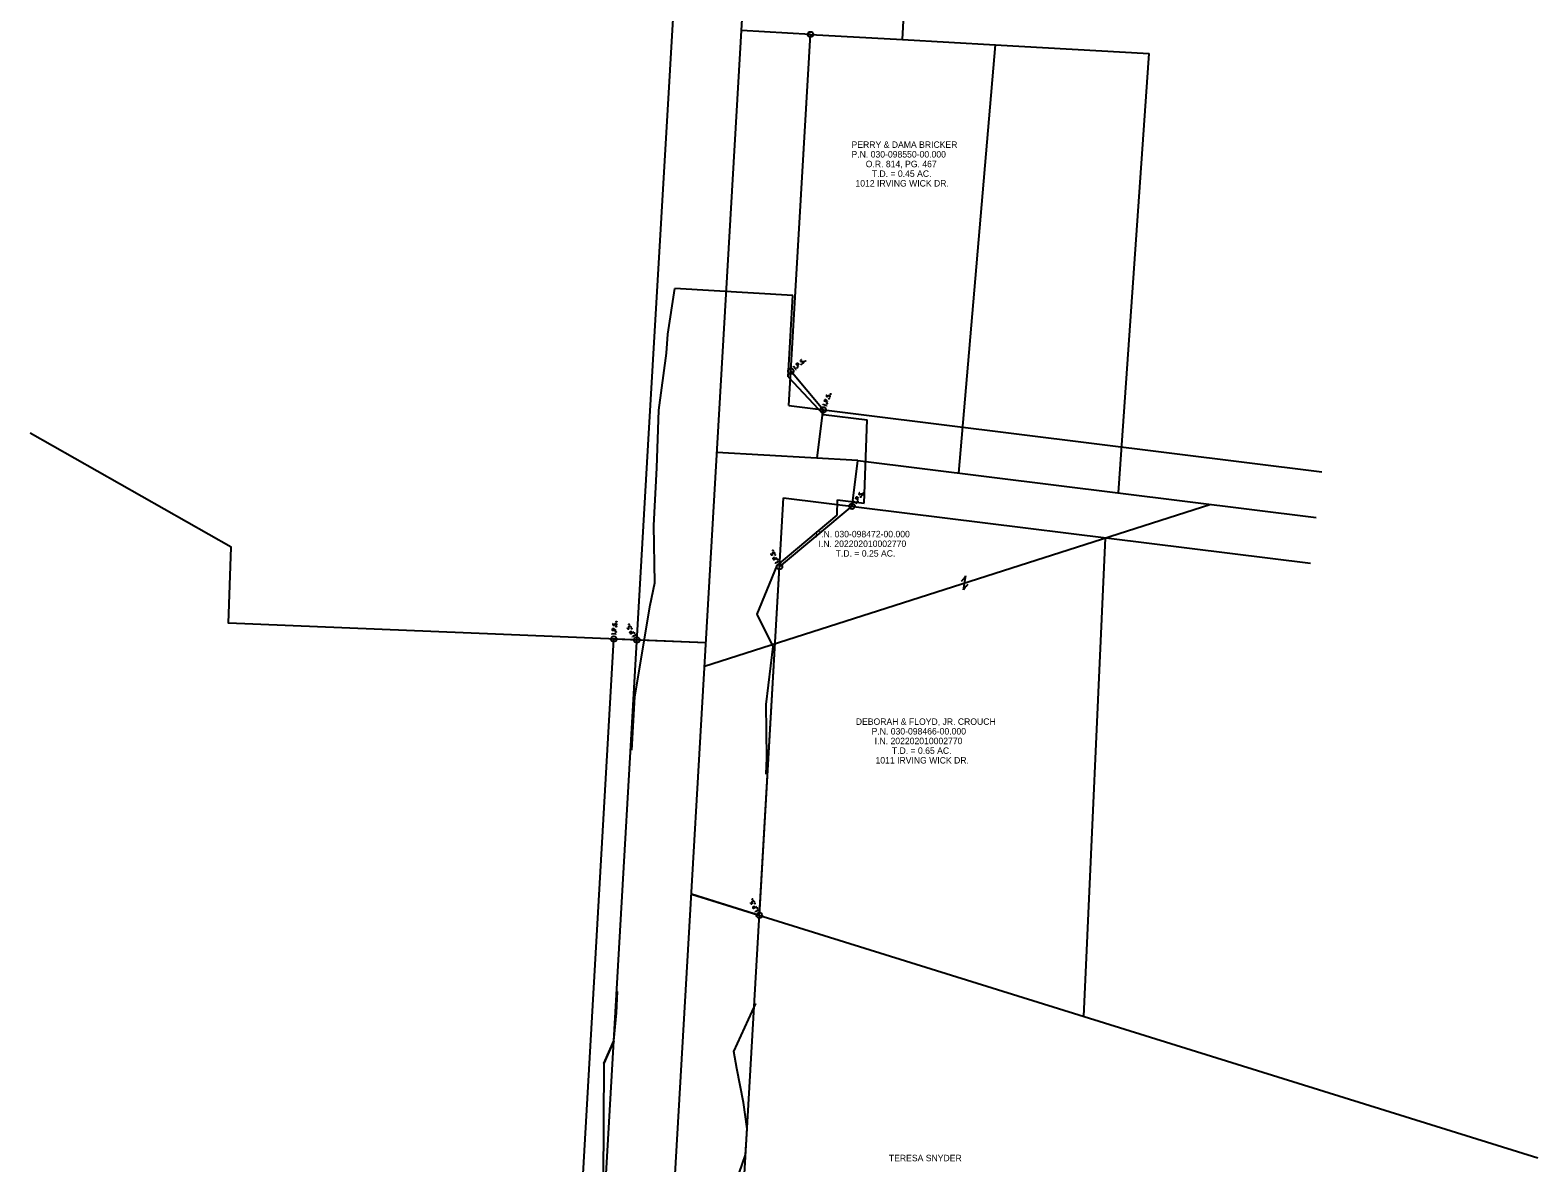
# Model space of a CAD drawing. Extents: x 1972534 to 2012581, y 730948 to 738786.
# Drawn here: x 1973763 to 1974418, y 737810 to 738302 of the extents above; entities that cross this region are included whole.
import ezdxf

# ---------------------------------------------------------------- set-up
doc = ezdxf.new("R2010")
doc.units = 0
for name, color, linetype in [('_CIVIL_CONSTRUCTION', 7, 'Continuous'), ('DR_P_GenericNode', 7, 'Continuous'), ('DR_X_Storm_Sewer', 7, 'Continuous'), ('GE_X_Alignment_1000_Cardinal_Points', 7, 'Continuous'), ('PF_X_Ground_Line', 7, 'Continuous'), ('SC_ProfileRun4', 7, 'Continuous'), ('UT_P_Water', 7, 'Continuous'), ('UT_P_Water_Cells', 7, 'Continuous')]:
    doc.layers.add(name, color=color, linetype=linetype)

msp = doc.modelspace()

# ---------------------------------------------------------------- linework, layer by layer
at = {"layer": 'DR_P_GenericNode'}
for points in [[(1974094.28, 738155.41), (1974094.55, 738155.64)], [(1974095.45, 738154.31), (1974094.42, 738155.53)], [(1974096.65, 738155.32), (1974095.61, 738156.54), (1974096.01, 738156.88), (1974096.06, 738156.91), (1974096.14, 738156.94), (1974096.18, 738156.94), (1974096.22, 738156.94), (1974096.29, 738156.92), (1974096.36, 738156.9), (1974096.44, 738156.84), (1974096.54, 738156.72), (1974096.56, 738156.67), (1974096.6, 738156.6), (1974096.62, 738156.51), (1974096.61, 738156.45), (1974096.6, 738156.41), (1974096.58, 738156.35), (1974096.52, 738156.29), (1974096.12, 738155.94)], [(1974097.97, 738158.4), (1974097.94, 738158.41), (1974097.9, 738158.41), (1974097.8, 738158.37), (1974097.69, 738158.31), (1974097.62, 738158.25), (1974097.6, 738158.23), (1974097.51, 738158.11), (1974097.47, 738157.97), (1974097.48, 738157.85), (1974097.53, 738157.76), (1974097.57, 738157.7), (1974097.66, 738157.64), (1974097.78, 738157.63), (1974098.49, 738157.73), (1974098.56, 738157.73), (1974098.61, 738157.71), (1974098.68, 738157.66), (1974098.73, 738157.6), (1974098.77, 738157.54), (1974098.79, 738157.49), (1974098.82, 738157.43), (1974098.83, 738157.38), (1974098.84, 738157.34), (1974098.84, 738157.29), (1974098.83, 738157.25), (1974098.81, 738157.2), (1974098.8, 738157.17), (1974098.73, 738157.09), (1974098.61, 738156.99), (1974098.52, 738156.95), (1974098.35, 738156.92), (1974098.24, 738156.92)], [(1974097.76, 738156.55), (1974097.8, 738156.58), (1974097.84, 738156.59), (1974097.9, 738156.57), (1974097.94, 738156.52), (1974097.95, 738156.46), (1974097.94, 738156.42), (1974097.9, 738156.39), (1974097.86, 738156.38), (1974097.8, 738156.4), (1974097.76, 738156.45), (1974097.75, 738156.51), (1974097.76, 738156.55)], [(1974099.42, 738157.96), (1974099.46, 738158), (1974099.5, 738158), (1974099.56, 738157.98), (1974099.6, 738157.94), (1974099.61, 738157.88), (1974099.6, 738157.84), (1974099.56, 738157.8), (1974099.52, 738157.8), (1974099.46, 738157.81), (1974099.42, 738157.86), (1974099.41, 738157.92), (1974099.42, 738157.96)], [(1974095.32, 738154.19), (1974095.59, 738154.42)], [(1974096.05, 738155.09), (1974096.09, 738155.13), (1974096.13, 738155.13), (1974096.19, 738155.11), (1974096.23, 738155.06), (1974096.23, 738155), (1974096.23, 738154.96), (1974096.18, 738154.93), (1974096.14, 738154.93), (1974096.08, 738154.94), (1974096.04, 738154.99), (1974096.04, 738155.05), (1974096.05, 738155.09)], [(1974108.98, 738143.25), (1974108.95, 738143.24), (1974108.92, 738143.22), (1974108.85, 738143.14), (1974108.78, 738143.04), (1974108.75, 738142.95), (1974108.74, 738142.92), (1974108.72, 738142.77), (1974108.75, 738142.63), (1974108.82, 738142.53), (1974108.91, 738142.47), (1974108.98, 738142.45), (1974109.08, 738142.43), (1974109.19, 738142.48), (1974109.76, 738142.92), (1974109.82, 738142.95), (1974109.88, 738142.96), (1974109.96, 738142.95), (1974110.03, 738142.93), (1974110.1, 738142.89), (1974110.14, 738142.86), (1974110.19, 738142.82), (1974110.23, 738142.78), (1974110.26, 738142.75), (1974110.28, 738142.7), (1974110.29, 738142.66), (1974110.3, 738142.61), (1974110.3, 738142.58), (1974110.28, 738142.48), (1974110.23, 738142.34), (1974110.17, 738142.25), (1974110.04, 738142.15), (1974109.93, 738142.09)], [(1974110.46, 738143.58), (1974110.48, 738143.63), (1974110.51, 738143.65), (1974110.57, 738143.66), (1974110.63, 738143.64), (1974110.67, 738143.59), (1974110.68, 738143.55), (1974110.66, 738143.5), (1974110.62, 738143.48), (1974110.57, 738143.47), (1974110.51, 738143.49), (1974110.47, 738143.54), (1974110.46, 738143.58)], [(1974107.22, 738138.84), (1974107.35, 738139.17)], [(1974108.79, 738138.45), (1974107.29, 738139)], [(1974109.33, 738139.92), (1974107.83, 738140.47), (1974108.01, 738140.97), (1974108.04, 738141.02), (1974108.1, 738141.08), (1974108.13, 738141.1), (1974108.17, 738141.12), (1974108.24, 738141.14), (1974108.31, 738141.15), (1974108.41, 738141.14), (1974108.55, 738141.09), (1974108.6, 738141.06), (1974108.66, 738141.01), (1974108.73, 738140.94), (1974108.75, 738140.88), (1974108.76, 738140.84), (1974108.77, 738140.78), (1974108.75, 738140.7), (1974108.56, 738140.2)], [(1974108.73, 738138.28), (1974108.85, 738138.61)], [(1974108.92, 738139.42), (1974108.94, 738139.47), (1974108.97, 738139.5), (1974109.03, 738139.51), (1974109.09, 738139.49), (1974109.13, 738139.44), (1974109.14, 738139.4), (1974109.12, 738139.35), (1974109.08, 738139.33), (1974109.03, 738139.31), (1974108.97, 738139.33), (1974108.93, 738139.38), (1974108.92, 738139.42)], [(1974109.7, 738141.53), (1974109.72, 738141.58), (1974109.75, 738141.6), (1974109.81, 738141.62), (1974109.87, 738141.6), (1974109.91, 738141.55), (1974109.92, 738141.51), (1974109.9, 738141.46), (1974109.87, 738141.43), (1974109.81, 738141.42), (1974109.75, 738141.44), (1974109.71, 738141.49), (1974109.7, 738141.53)], [(1974120.36, 738096.91), (1974120.57, 738097.19)], [(1974121.77, 738096.12), (1974120.47, 738097.05)], [(1974122.68, 738097.39), (1974121.38, 738098.32), (1974121.69, 738098.75), (1974121.73, 738098.79), (1974121.79, 738098.84), (1974121.83, 738098.85), (1974121.87, 738098.86), (1974121.95, 738098.86), (1974122.02, 738098.85), (1974122.12, 738098.81), (1974122.24, 738098.72), (1974122.27, 738098.68), (1974122.32, 738098.62), (1974122.37, 738098.54), (1974122.37, 738098.48), (1974122.37, 738098.44), (1974122.36, 738098.38), (1974122.32, 738098.3), (1974122.01, 738097.87)], [(1974121.67, 738095.97), (1974121.87, 738096.26)], [(1974122.15, 738097.02), (1974122.18, 738097.07), (1974122.22, 738097.08), (1974122.28, 738097.08), (1974122.34, 738097.04), (1974122.36, 738096.98), (1974122.36, 738096.94), (1974122.33, 738096.9), (1974122.29, 738096.89), (1974122.23, 738096.89), (1974122.17, 738096.92), (1974122.15, 738096.98), (1974122.15, 738097.02)], [(1974123.22, 738100.7), (1974123.19, 738100.7), (1974123.15, 738100.69), (1974123.06, 738100.63), (1974122.97, 738100.55), (1974122.92, 738100.47), (1974122.9, 738100.45), (1974122.85, 738100.31), (1974122.84, 738100.17), (1974122.87, 738100.04), (1974122.94, 738099.97), (1974123, 738099.92), (1974123.1, 738099.88), (1974123.22, 738099.9), (1974123.88, 738100.18), (1974123.96, 738100.19), (1974124.01, 738100.18), (1974124.08, 738100.15), (1974124.15, 738100.11), (1974124.2, 738100.06), (1974124.23, 738100.02), (1974124.27, 738099.96), (1974124.3, 738099.92), (1974124.32, 738099.88), (1974124.33, 738099.83), (1974124.33, 738099.79), (1974124.33, 738099.74), (1974124.32, 738099.7), (1974124.27, 738099.61), (1974124.18, 738099.49), (1974124.1, 738099.42), (1974123.95, 738099.36), (1974123.83, 738099.33)], [(1974123.46, 738098.85), (1974123.49, 738098.9), (1974123.53, 738098.91), (1974123.59, 738098.91), (1974123.64, 738098.87), (1974123.67, 738098.81), (1974123.67, 738098.77), (1974123.64, 738098.73), (1974123.6, 738098.71), (1974123.54, 738098.72), (1974123.48, 738098.75), (1974123.46, 738098.81), (1974123.46, 738098.85)], [(1974124.73, 738100.63), (1974124.76, 738100.67), (1974124.8, 738100.68), (1974124.86, 738100.68), (1974124.91, 738100.64), (1974124.94, 738100.59), (1974124.94, 738100.55), (1974124.91, 738100.5), (1974124.87, 738100.49), (1974124.81, 738100.49), (1974124.75, 738100.53), (1974124.73, 738100.58), (1974124.73, 738100.63)], [(1974084.62, 738074.24), (1974084.61, 738074.21), (1974084.6, 738074.17), (1974084.62, 738074.07), (1974084.65, 738073.95), (1974084.69, 738073.87), (1974084.7, 738073.84), (1974084.8, 738073.73), (1974084.93, 738073.66), (1974085.05, 738073.63), (1974085.15, 738073.66), (1974085.22, 738073.7), (1974085.3, 738073.76), (1974085.34, 738073.88), (1974085.39, 738074.59), (1974085.41, 738074.67), (1974085.45, 738074.71), (1974085.5, 738074.76), (1974085.57, 738074.8), (1974085.64, 738074.82), (1974085.69, 738074.84), (1974085.76, 738074.84), (1974085.81, 738074.85), (1974085.86, 738074.85), (1974085.91, 738074.83), (1974085.94, 738074.82), (1974085.99, 738074.79), (1974086.01, 738074.77), (1974086.07, 738074.68), (1974086.14, 738074.55), (1974086.16, 738074.45), (1974086.15, 738074.28), (1974086.12, 738074.17)], [(1974085.38, 738075.55), (1974085.35, 738075.6), (1974085.36, 738075.64), (1974085.39, 738075.7), (1974085.45, 738075.72), (1974085.51, 738075.72), (1974085.54, 738075.7), (1974085.57, 738075.65), (1974085.56, 738075.61), (1974085.53, 738075.56), (1974085.48, 738075.53), (1974085.42, 738075.54), (1974085.38, 738075.55)], [(1974087.33, 738072.25), (1974085.9, 738071.52), (1974085.66, 738071.99), (1974085.65, 738072.04), (1974085.63, 738072.12), (1974085.64, 738072.17), (1974085.65, 738072.21), (1974085.68, 738072.27), (1974085.73, 738072.33), (1974085.8, 738072.4), (1974085.94, 738072.47), (1974085.99, 738072.48), (1974086.07, 738072.5), (1974086.16, 738072.5), (1974086.22, 738072.48), (1974086.26, 738072.46), (1974086.3, 738072.42), (1974086.36, 738072.35), (1974086.6, 738071.88)], [(1974086.38, 738073.62), (1974086.36, 738073.66), (1974086.36, 738073.7), (1974086.39, 738073.76), (1974086.45, 738073.79), (1974086.51, 738073.78), (1974086.55, 738073.76), (1974086.57, 738073.71), (1974086.56, 738073.67), (1974086.53, 738073.62), (1974086.48, 738073.59), (1974086.42, 738073.6), (1974086.38, 738073.62)], [(1974086.7, 738069.97), (1974086.54, 738070.29)], [(1974088.04, 738070.86), (1974086.62, 738070.13)], [(1974087.41, 738071.62), (1974087.39, 738071.67), (1974087.4, 738071.71), (1974087.43, 738071.76), (1974087.48, 738071.79), (1974087.54, 738071.78), (1974087.58, 738071.77), (1974087.6, 738071.72), (1974087.6, 738071.68), (1974087.57, 738071.62), (1974087.51, 738071.59), (1974087.45, 738071.6), (1974087.41, 738071.62)], [(1974088.13, 738070.71), (1974087.96, 738071.02)], [(1974016.11, 738043.9), (1974016.08, 738043.87), (1974016.06, 738043.84), (1974016.01, 738043.75), (1974015.98, 738043.63), (1974015.98, 738043.54), (1974015.97, 738043.51), (1974016, 738043.36), (1974016.07, 738043.23), (1974016.17, 738043.15), (1974016.27, 738043.12), (1974016.34, 738043.12), (1974016.44, 738043.14), (1974016.54, 738043.22), (1974016.95, 738043.8), (1974017, 738043.86), (1974017.05, 738043.88), (1974017.13, 738043.89), (1974017.21, 738043.89), (1974017.28, 738043.87), (1974017.33, 738043.86), (1974017.39, 738043.83), (1974017.44, 738043.81), (1974017.48, 738043.79), (1974017.51, 738043.75), (1974017.54, 738043.72), (1974017.56, 738043.67), (1974017.57, 738043.64), (1974017.58, 738043.54), (1974017.57, 738043.38), (1974017.54, 738043.29), (1974017.44, 738043.15), (1974017.36, 738043.06)], [(1974017.42, 738044.64), (1974017.43, 738044.69), (1974017.46, 738044.73), (1974017.51, 738044.76), (1974017.57, 738044.75), (1974017.62, 738044.72), (1974017.64, 738044.68), (1974017.64, 738044.63), (1974017.61, 738044.59), (1974017.56, 738044.56), (1974017.5, 738044.57), (1974017.45, 738044.6), (1974017.42, 738044.64)], [(1974015.73, 738039.16), (1974015.75, 738039.51)], [(1974017.34, 738039.24), (1974015.74, 738039.33)], [(1974017.42, 738040.81), (1974015.83, 738040.9), (1974015.86, 738041.43), (1974015.87, 738041.48), (1974015.9, 738041.56), (1974015.93, 738041.59), (1974015.96, 738041.62), (1974016.02, 738041.66), (1974016.09, 738041.69), (1974016.19, 738041.7), (1974016.34, 738041.7), (1974016.39, 738041.68), (1974016.46, 738041.66), (1974016.55, 738041.61), (1974016.58, 738041.56), (1974016.61, 738041.53), (1974016.63, 738041.47), (1974016.64, 738041.38), (1974016.61, 738040.85)], [(1974017.18, 738040.21), (1974017.18, 738040.27), (1974017.21, 738040.3), (1974017.26, 738040.33), (1974017.32, 738040.33), (1974017.37, 738040.29), (1974017.39, 738040.26), (1974017.39, 738040.2), (1974017.36, 738040.17), (1974017.31, 738040.14), (1974017.25, 738040.14), (1974017.2, 738040.18), (1974017.18, 738040.21)], [(1974017.3, 738042.46), (1974017.31, 738042.51), (1974017.33, 738042.55), (1974017.38, 738042.58), (1974017.45, 738042.57), (1974017.5, 738042.54), (1974017.52, 738042.5), (1974017.52, 738042.45), (1974017.49, 738042.42), (1974017.44, 738042.39), (1974017.37, 738042.39), (1974017.33, 738042.42), (1974017.3, 738042.46)], [(1974017.33, 738039.07), (1974017.35, 738039.42)], [(1974022.24, 738042.06), (1974022.23, 738042.03), (1974022.22, 738041.99), (1974022.24, 738041.88), (1974022.29, 738041.77), (1974022.33, 738041.69), (1974022.35, 738041.66), (1974022.46, 738041.56), (1974022.59, 738041.5), (1974022.71, 738041.49), (1974022.81, 738041.52), (1974022.88, 738041.56), (1974022.95, 738041.63), (1974022.98, 738041.76), (1974022.98, 738042.47), (1974022.99, 738042.54), (1974023.02, 738042.59), (1974023.07, 738042.65), (1974023.14, 738042.69), (1974023.21, 738042.72), (1974023.26, 738042.74), (1974023.32, 738042.75), (1974023.37, 738042.76), (1974023.42, 738042.76), (1974023.47, 738042.75), (1974023.51, 738042.74), (1974023.55, 738042.71), (1974023.58, 738042.69), (1974023.64, 738042.61), (1974023.73, 738042.48), (1974023.76, 738042.39), (1974023.76, 738042.22), (1974023.74, 738042.1)], [(1974022.88, 738043.43), (1974022.85, 738043.47), (1974022.86, 738043.51), (1974022.88, 738043.57), (1974022.94, 738043.6), (1974023, 738043.6), (1974023.04, 738043.59), (1974023.06, 738043.54), (1974023.06, 738043.5), (1974023.04, 738043.44), (1974022.98, 738043.41), (1974022.92, 738043.41), (1974022.88, 738043.43)], [(1974025.09, 738040.3), (1974023.74, 738039.45), (1974023.46, 738039.9), (1974023.44, 738039.95), (1974023.42, 738040.03), (1974023.42, 738040.07), (1974023.43, 738040.11), (1974023.46, 738040.18), (1974023.49, 738040.24), (1974023.56, 738040.32), (1974023.69, 738040.4), (1974023.74, 738040.41), (1974023.82, 738040.44), (1974023.92, 738040.44), (1974023.97, 738040.43), (1974024.01, 738040.41), (1974024.06, 738040.38), (1974024.12, 738040.31), (1974024.4, 738039.86)], [(1974024.04, 738041.58), (1974024.01, 738041.62), (1974024.01, 738041.66), (1974024.04, 738041.72), (1974024.09, 738041.75), (1974024.15, 738041.75), (1974024.19, 738041.74), (1974024.22, 738041.69), (1974024.22, 738041.65), (1974024.19, 738041.59), (1974024.14, 738041.56), (1974024.08, 738041.56), (1974024.04, 738041.58)], [(1974024.66, 738037.97), (1974024.47, 738038.27)], [(1974025.92, 738038.97), (1974024.57, 738038.12)], [(1974025.23, 738039.67), (1974025.2, 738039.72), (1974025.21, 738039.76), (1974025.23, 738039.81), (1974025.29, 738039.85), (1974025.35, 738039.84), (1974025.38, 738039.83), (1974025.41, 738039.78), (1974025.41, 738039.74), (1974025.39, 738039.69), (1974025.33, 738039.65), (1974025.27, 738039.65), (1974025.23, 738039.67)], [(1974026.02, 738038.82), (1974025.83, 738039.12)], [(1974075.79, 737922.72), (1974075.78, 737922.69), (1974075.77, 737922.65), (1974075.78, 737922.55), (1974075.82, 737922.43), (1974075.86, 737922.35), (1974075.88, 737922.32), (1974075.98, 737922.21), (1974076.1, 737922.14), (1974076.23, 737922.12), (1974076.33, 737922.15), (1974076.39, 737922.19), (1974076.47, 737922.26), (1974076.51, 737922.37), (1974076.55, 737923.09), (1974076.57, 737923.16), (1974076.6, 737923.2), (1974076.66, 737923.26), (1974076.72, 737923.3), (1974076.8, 737923.32), (1974076.85, 737923.34), (1974076.91, 737923.35), (1974076.97, 737923.35), (1974077.01, 737923.35), (1974077.06, 737923.34), (1974077.1, 737923.32), (1974077.14, 737923.3), (1974077.17, 737923.27), (1974077.23, 737923.19), (1974077.3, 737923.06), (1974077.32, 737922.96), (1974077.32, 737922.79), (1974077.29, 737922.67)], [(1974076.52, 737924.05), (1974076.49, 737924.1), (1974076.5, 737924.14), (1974076.53, 737924.19), (1974076.58, 737924.22), (1974076.64, 737924.22), (1974076.68, 737924.2), (1974076.71, 737924.15), (1974076.7, 737924.11), (1974076.67, 737924.06), (1974076.61, 737924.03), (1974076.55, 737924.03), (1974076.52, 737924.05)], [(1974078.53, 737920.79), (1974077.12, 737920.03), (1974076.87, 737920.49), (1974076.86, 737920.54), (1974076.84, 737920.62), (1974076.85, 737920.67), (1974076.85, 737920.71), (1974076.89, 737920.78), (1974076.93, 737920.83), (1974077.01, 737920.9), (1974077.14, 737920.97), (1974077.19, 737920.99), (1974077.26, 737921.01), (1974077.36, 737921.01), (1974077.42, 737920.99), (1974077.46, 737920.97), (1974077.5, 737920.93), (1974077.56, 737920.86), (1974077.81, 737920.4)], [(1974077.56, 737922.13), (1974077.53, 737922.18), (1974077.54, 737922.22), (1974077.57, 737922.27), (1974077.62, 737922.3), (1974077.68, 737922.3), (1974077.72, 737922.28), (1974077.75, 737922.23), (1974077.74, 737922.19), (1974077.71, 737922.14), (1974077.66, 737922.11), (1974077.6, 737922.11), (1974077.56, 737922.13)], [(1974078.63, 737920.15), (1974078.6, 737920.2), (1974078.61, 737920.24), (1974078.64, 737920.3), (1974078.69, 737920.33), (1974078.75, 737920.32), (1974078.79, 737920.3), (1974078.82, 737920.26), (1974078.81, 737920.21), (1974078.78, 737920.16), (1974078.73, 737920.13), (1974078.67, 737920.14), (1974078.63, 737920.15)], [(1974079.36, 737919.26), (1974079.19, 737919.57)], [(1974077.95, 737918.49), (1974077.79, 737918.8)], [(1974079.28, 737919.41), (1974077.87, 737918.65)]]:
    msp.add_lwpolyline(points, dxfattribs=at)
for centre in [(1974101.81, 738299.75), (1974093.26, 738153.49), (1974107.28, 738136.67), (1974119.84, 738094.8), (1974088.34, 738068.55), (1974016.42, 738037.1), (1974026.41, 738036.68), (1974079.62, 737917.1)]:
    msp.add_circle(centre, 1.2, dxfattribs=at)
at = {"layer": 'DR_X_Storm_Sewer'}
for p, q in [((1974094.18, 738186.4), (1974042.83, 738189.4)), ((1974092.11, 738150.99), (1974094.18, 738186.4)), ((1974092.11, 738150.99), (1974107.42, 738134.63)), ((1974107.42, 738134.63), (1974126.46, 738132.27)), ((1974125.19, 738096.15), (1974126.46, 738132.27)), ((1974113.37, 738090.96), (1974113.6, 738097.59)), ((1974113.6, 738097.59), (1974125.19, 738096.15)), ((1974087.3, 738069.05), (1974113.37, 738090.96)), ((1974016.41, 737862.55), (1974012.05, 737852.7)), ((1974012.05, 737852.7), (1974011.77, 737801.97))]:
    msp.add_line(p, q, dxfattribs=at)
for points in [[(1974024.27, 737988.84), (1974025.52, 738012), (1974032.14, 738051.82), (1974034.21, 738061.5), (1974033.84, 738086.4), (1974035.04, 738111.43), (1974036.02, 738136.5), (1974039.34, 738161.36), (1974039.8, 738169.54), (1974042.83, 738189.4)], [(1974082.57, 738008.62), (1974082.57, 738008.62), (1974085.63, 738033.89), (1974078.7, 738047.94), (1974087.3, 738069.05)], [(1974082.56, 737978.36), (1974082.88, 737985.46), (1974082.56, 738008.71)], [(1974012.05, 737852.7), (1974016.41, 737862.55), (1974017.54, 737874.81), (1974018.01, 737884.04)], [(1974053.5, 737534.36), (1974053.58, 737559.62), (1974052.76, 737585.5), (1974061.07, 737597.4), (1974064.74, 737658.78), (1974064.74, 737658.78), (1974065.33, 737669), (1974065.33, 737669), (1974059.79, 737684.21), (1974063.48, 737709.1), (1974064.03, 737734.22), (1974065.03, 737759.11), (1974067.35, 737779.85), (1974068.08, 737797.16), (1974073.63, 737813.1), (1974074.28, 737824.34), (1974072.7, 737835.76), (1974069.86, 737850.62), (1974068.53, 737857.98), (1974078.11, 737878.86)]]:
    msp.add_lwpolyline(points, dxfattribs=at)
at = {"layer": 'GE_X_Alignment_1000_Cardinal_Points'}
for p, q in [((1974031.44, 738123.95), (1974070.08, 738785.54)), ((1974092.39, 738138.52), (1974101.81, 738299.75)), ((1974092.39, 738138.52), (1974323.87, 738109.75)), ((1973994.36, 737480.25), (1974031.44, 738123.95)), ((1974054.27, 737476.97), (1974090.07, 738098.5)), ((1974090.07, 738098.5), (1974318.94, 738070.05))]:
    msp.add_line(p, q, dxfattribs=at)
at = {"layer": 'PF_X_Ground_Line'}
for p, q in [((1974061.39, 738122.22), (1974092.99, 738663.34)), ((1974024.31, 737478.61), (1974061.39, 738122.22)), ((1974122.31, 738114.65), (1974061.15, 738118.19)), ((1974122.31, 738114.65), (1974321.41, 738089.9))]:
    msp.add_line(p, q, dxfattribs=at)
at = {"layer": 'SC_ProfileRun4'}
for p, q in [((1974101.81, 738299.75), (1974071.86, 738301.5)), ((1974093.26, 738153.49), (1974101.81, 738299.75)), ((1974107.28, 738136.67), (1974093.26, 738153.49)), ((1974104.67, 738115.67), (1974107.28, 738136.67)), ((1974119.84, 738094.8), (1974122.31, 738114.65)), ((1974055.81, 738025.38), (1974275.28, 738095.63)), ((1974088.34, 738068.55), (1974119.84, 738094.8)), ((1974079.62, 737917.1), (1974088.34, 738068.55)), ((1973984.37, 737480.8), (1974016.42, 738037.1)), ((1974056.39, 738035.45), (1974016.42, 738037.1)), ((1974079.62, 737917.1), (1974050.1, 737926.3))]:
    msp.add_line(p, q, dxfattribs=at)
at = {"layer": 'UT_P_Water'}
for p, q in [((1974235.55, 738100.57), (1974248.94, 738291.4)), ((1974220.54, 737873.2), (1974229.93, 738081.11)), ((1974168.26, 738058.46), (1974169.31, 738064.62)), ((1974168.78, 738061.54), (1974168.78, 738061.54)), ((1974050.1, 737926.3), (1974417.68, 737811.79))]:
    msp.add_line(p, q, dxfattribs=at)
for points in [[(1974141.74, 738297.49), (1974182.05, 738295.2), (1974166.08, 738109.2)], [(1974182.05, 738295.2), (1974248.94, 738291.4)], [(1974056.32, 738035.45), (1973849.08, 738044.01), (1973850.25, 738076.98), (1973762.94, 738126.53)]]:
    msp.add_lwpolyline(points, dxfattribs=at)
for centre, start, end in [((1974164.41, 738066.75), 303.82881, 336.47133), ((1974173.15, 738056.33), 123.82881, 156.47133)]:
    msp.add_arc(centre, 5.34, start, end, dxfattribs=at)
at = {"layer": 'UT_P_Water_Cells'}
for p, q in [((1974141.74, 738297.49), (1974166.77, 738725.89)), ((1974101.81, 738299.75), (1974141.74, 738297.49))]:
    msp.add_line(p, q, dxfattribs=at)

# ---------------------------------------------------------------- texts
at = {"layer": '_CIVIL_CONSTRUCTION'}
for s, p in [('P.N. 030-098550-00.000', (1974119.62, 738246.28)), ('PERRY & DAMA BRICKER', (1974119.64, 738250.48)), ('O.R. 814, PG. 467', (1974125.81, 738242.08)), ('T.D. = 0.45 AC.', (1974128.43, 738237.88)), ('1012 IRVING WICK DR.', (1974121.33, 738233.68)), ('P.N. 030-098472-00.000', (1974103.95, 738081.32)), ('I.N. 202202010002770', (1974105.3, 738077.12)), ('T.D. = 0.25 AC.', (1974112.76, 738072.92)), ('DEBORAH & FLOYD, JR. CROUCH', (1974121.49, 737999.85)), ('P.N. 030-098466-00.000', (1974128.34, 737995.65)), ('I.N. 202202010002770', (1974129.69, 737991.45)), ('1011 IRVING WICK DR.', (1974130.05, 737983.05)), ('T.D. = 0.65 AC.', (1974137.15, 737987.25)), ('TERESA SNYDER', (1974135.85, 737810.29))]:
    msp.add_text(s, height=2.8, dxfattribs=at).set_placement(p)

doc.saveas('drawing.dxf')
